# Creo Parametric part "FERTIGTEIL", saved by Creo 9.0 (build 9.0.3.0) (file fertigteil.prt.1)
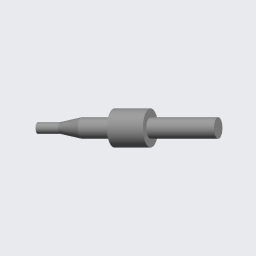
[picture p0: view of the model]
Materials in the file: S235JRG2

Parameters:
  BENENNUNG = "XXX"
  DATUM = "XX.XX.XX"
  ERSTELLER = "ARINDA"
  TEILETYP = "Fertigungsteil"
  PTC_MASTER_MATERIAL = "S235JRG2"
  SELECT_EN_NAME = "S235JRG2"
  SELECT_DIN_NAME = "RSt37-2"
  SELECT_DIN_NUMBER = "1.0038"
  SELECT_ASTM_NAME = "A 283 M Grade 2"
  MATERIAL_GROUP = "ME_ST_Baustahl"
  STANDARD_EN_DELIVERYSPEC = "DIN EN 10025"
  STANDARD_DIN_DELIVERYSPEC = "DIN 17100"

Other parameters: MASSE

Created from: ARINDA-STARTTEIL.PRT

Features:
  1. coordinate system "CS0"
  2. datum plane "DTM1", "T_RECHTS_Y-Z"
  3. datum plane "DTM2", "T_OBEN_X-Z"
  4. datum plane "DTM3", "T_VORNE_X-Y"
  5. datum axis "T_X-ACHSE"
  6. datum axis "A_1"
  7. datum axis "A_2"
  8. feature "Körper Hinzufügen ID 40"
  9. revolved cut "Drehen 1"

Other named items: T_BASIC, T_Y-ACHSE, T_Z-ACHSE, T_X-ACHSE_1, T_Y-ACHSE_1, T_Z-ACHSE_1, T_BASIC_1

Layers: 00_STD-ACHSEN, 00_STD-EBENEN, 00_STD-KOORDSYS, VOLUMENGEOMETRIE

Surfaces: 8 cylinder, 4 plane, 2 cone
